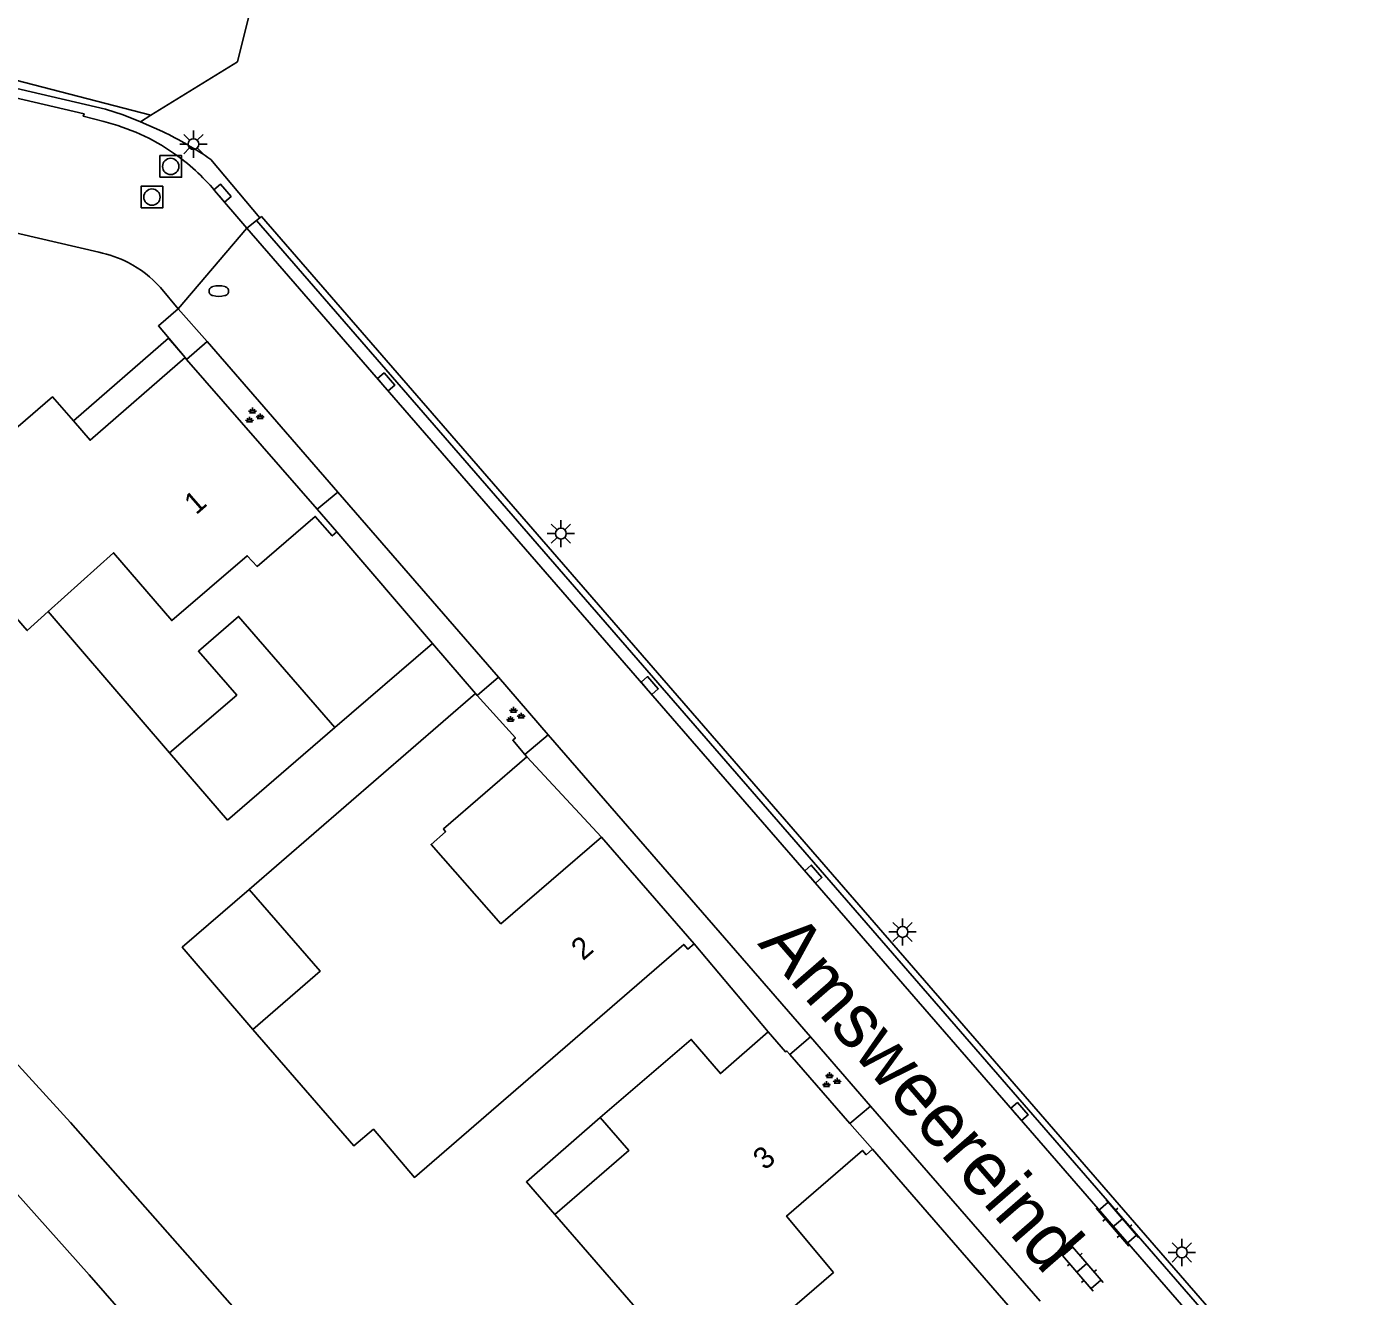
# Model space of a CAD drawing. Extents: x 128999 to 131010, y 395498 to 399007.
# Drawn here: x 129282.9 to 129344, y 397464.4 to 397522.8 of the extents above; entities that cross this region are included whole.
import ezdxf

# ---------------------------------------------------------------- set-up
doc = ezdxf.new("R2010")
doc.units = 0
for name, color, linetype in [('gg-afsc-faunaraster', 7, 'Continuous'), ('gg-afsc-muur', 7, 'Continuous'), ('gg-anno-huisnummerreeks BGT', 7, 'Continuous'), ('gg-anno-openbare ruimte label', 7, 'Continuous'), ('gg-bbg-bijgebouw', 7, 'Continuous'), ('gg-bbg-hoofdgebouw', 7, 'Continuous'), ('gg-bbg-luifel en loopbrug', 7, 'Continuous'), ('gg-bbg-onder overbouw', 7, 'Continuous'), ('gg-bbg-pand overbouw', 7, 'Continuous'), ('gg-knt-verharding', 7, 'Continuous'), ('gg-knt-verharding nz', 7, 'Continuous'), ('gg-kntw-bovenkant insteek waterloop', 7, 'Continuous'), ('gg-kntw-waterlijn', 7, 'Continuous'), ('gt-grn-groengrens', 7, 'Continuous'), ('gt-grn-weggrens', 7, 'Continuous'), ('gt-symb-brandkraan', 7, 'Continuous'), ('gt-symb-groenvak', 7, 'Continuous'), ('gt-symb-klinker verharding', 7, 'Continuous'), ('gt-symb-kolk', 7, 'Continuous'), ('gt-symb-lichtmast', 7, 'Continuous'), ('gt-symb-rioolschacht', 7, 'Continuous')]:
    doc.layers.add(name, color=color, linetype=linetype)

# ---------------------------------------------------------------- blocks, each defined once
blk = doc.blocks.new('gt0-LMAST')
at = {"layer": 'gt-symb-lichtmast'}
for p, q in [((-0.005, 0.246), (-0.005, 0.621)), ((-0.182, 0.173), (-0.447, 0.438)), ((0.172, 0.173), (0.437, 0.438)), ((-0.255, -0.004), (-0.63, -0.004)), ((-0.182, -0.181), (-0.447, -0.446)), ((-0.005, -0.254), (-0.005, -0.629)), ((0.437, -0.446), (0.172, -0.181)), ((0.245, -0.004), (0.62, -0.004))]:
    blk.add_line(p, q, dxfattribs=at)
blk.add_circle((-0.005, -0.004), 0.25, dxfattribs=at)
blk = doc.blocks.new('gt0-KOLK')
at = {"layer": 'gt-symb-kolk'}
blk.add_lwpolyline([(0, 0), (0.375, 0), (0.375, 0.4), (-0.375, 0.4), (-0.375, 0), (0, 0)], dxfattribs=at)
blk = doc.blocks.new('gt0-KL1')
at = {"layer": 'gt-symb-klinker verharding'}
for p, q in [((-1.15, 0.3), (1.15, 0.3)), ((-1, -0.3), (-1, 0.3)), ((-0.5, 0.3), (-0.5, 0.45)), ((0, -0.3), (0, 0.3)), ((0.5, 0.3), (0.5, 0.45)), ((1, -0.3), (1, 0.3)), ((-1.15, -0.3), (1.15, -0.3)), ((-0.5, -0.45), (-0.5, -0.3)), ((0.5, -0.45), (0.5, -0.3))]:
    blk.add_line(p, q, dxfattribs=at)
blk = doc.blocks.new('gt0-GRVAK')
at = {"layer": 'gt-symb-groenvak'}
for p, q in [((-0.11, 0.189), (-0.228, 0.24)), ((-0.182, 0.153), (0.088, 0.153)), ((-0.091, 0.211), (-0.156, 0.322)), ((-0.047, 0.214), (-0.047, 0.393)), ((-0.004, 0.211), (0.061, 0.322)), ((0.015, 0.189), (0.133, 0.24)), ((0.262, -0.052), (0.197, 0.059)), ((0.305, -0.049), (0.305, 0.13)), ((0.349, -0.052), (0.414, 0.059)), ((-0.245, -0.228), (-0.363, -0.177)), ((-0.318, -0.264), (-0.047, -0.264)), ((-0.226, -0.206), (-0.291, -0.095)), ((-0.183, -0.203), (-0.183, -0.024)), ((-0.139, -0.206), (-0.074, -0.095)), ((-0.12, -0.228), (-0.002, -0.177)), ((0.243, -0.074), (0.125, -0.023)), ((0.17, -0.11), (0.441, -0.11)), ((0.368, -0.074), (0.486, -0.023))]:
    blk.add_line(p, q, dxfattribs=at)
blk = doc.blocks.new('gt0-RS')
at = {"layer": 'gt-symb-rioolschacht'}
blk.add_lwpolyline([(-0.5, -0.5), (0.5, -0.5), (0.5, 0.5), (-0.5, 0.5)], close=True, dxfattribs=at)
blk.add_circle((0, 0), 0.375, dxfattribs=at)
blk = doc.blocks.new('gt0-BR')
at = {"layer": 'gt-symb-brandkraan'}
for centre, radius, start, end in [((-0.244, 0), 0.206, 107.56694, 252.43307), ((0.599, -2.664), 3, 106.89205, 107.56694), ((0, -0.691), 0.938, 73.10799, 106.89205), ((-0.599, -2.664), 3, 72.43309, 73.10799), ((0.244, 0), 0.206, 287.56695, 72.43309), ((0.599, 2.664), 3, 252.43307, 253.10797), ((0, 0.691), 0.938, 253.10797, 286.89206), ((-0.599, 2.664), 3, 286.89206, 287.56695)]:
    blk.add_arc(centre, radius, start, end, dxfattribs=at)

msp = doc.modelspace()

# ---------------------------------------------------------------- linework, layer by layer
at = {"layer": 'gg-afsc-faunaraster'}
for p, q in [((129289.126, 397518.003), (129288.116, 397518.456)), ((129293.598, 397514.027), (129291.348, 397516.722))]:
    msp.add_line(p, q, dxfattribs=at)
msp.add_lwpolyline([(129265.267, 397528.956), (129264.121, 397524.258), (129286.501, 397519.035), (129287.315, 397518.765), (129288.116, 397518.456)], dxfattribs=at)
msp.add_arc((129280.986, 397501.316), 18.566, 56.07553, 63.99691, dxfattribs=at)
at = {"layer": 'gg-afsc-muur'}
msp.add_line((129293.598, 397514.027), (129293.453, 397513.907), dxfattribs=at)
for points in [[(129339.555, 397452.636), (129343.606, 397456.151), (129293.453, 397513.907)], [(129338.819, 397451.59), (129344.015, 397456.113), (129293.672, 397514.088), (129293.598, 397514.027)]]:
    msp.add_lwpolyline(points, dxfattribs=at)
at = {"layer": 'gg-bbg-bijgebouw'}
for p, q in [((129297.055, 397490.584), (129292.119, 397486.323)), ((129292.119, 397486.323), (129289.448, 397489.428))]:
    msp.add_line(p, q, dxfattribs=at)
msp.add_lwpolyline([(129289.448, 397489.428), (129292.537, 397492.085), (129290.775, 397494.099), (129292.624, 397495.702), (129297.055, 397490.584)], dxfattribs=at)
at = {"layer": 'gg-bbg-hoofdgebouw'}
for p, q in [((129290.235, 397507.518), (129290.16, 397507.605)), ((129296.234, 397500.635), (129290.235, 397507.518)), ((129297.138, 397499.598), (129296.234, 397500.635)), ((129293.119, 397483.137), (129303.529, 397492.148)), ((129303.529, 397492.148), (129303.608, 397492.06)), ((129305.796, 397489.355), (129305.887, 397489.249)), ((129309.32, 397485.548), (129313.587, 397480.648)), ((129317.997, 397475.546), (129320.755, 397472.381)), ((129320.755, 397472.381), (129321.793, 397471.19))]:
    msp.add_line(p, q, dxfattribs=at)
for points in [[(129278.065, 397500.628), (129284.065, 397505.793), (129285.023, 397504.691)], [(129278.301, 397500.353), (129282.898, 397495.047), (129283.864, 397495.919)], [(129283.864, 397495.919), (129286.871, 397498.632), (129289.553, 397495.506), (129293.022, 397498.488), (129293.487, 397497.997), (129296.154, 397500.302), (129296.932, 397499.401), (129297.138, 397499.598)], [(129303.608, 397492.06), (129305.361, 397490.109), (129305.239, 397490.003), (129305.796, 397489.355)], [(129305.887, 397489.249), (129302.052, 397485.925), (129302.152, 397485.794), (129301.486, 397485.216), (129304.692, 397481.563), (129309.32, 397485.548)], [(129293.284, 397476.699), (129296.376, 397479.377), (129293.119, 397483.137)], [(129313.587, 397480.648), (129313.303, 397480.394), (129313.112, 397480.615), (129300.717, 397469.899), (129298.828, 397472.11), (129297.933, 397471.346), (129293.284, 397476.699)], [(129309.265, 397472.647), (129313.457, 397476.244), (129314.794, 397474.67), (129316.997, 397476.594)], [(129316.997, 397476.594), (129317.793, 397475.668), (129317.854, 397475.71), (129317.997, 397475.546)], [(129321.793, 397471.19), (129321.506, 397470.936), (129321.332, 397471.136), (129317.841, 397468.115), (129319.996, 397465.524), (129313.981, 397460.343), (129307.177, 397468.195)]]:
    msp.add_lwpolyline(points, dxfattribs=at)
at = {"layer": 'gg-bbg-luifel en loopbrug'}
for p, q in [((129301.552, 397494.453), (129297.138, 397499.598)), ((129289.448, 397489.428), (129283.864, 397495.919)), ((129297.055, 397490.584), (129301.552, 397494.453))]:
    msp.add_line(p, q, dxfattribs=at)
msp.add_lwpolyline([(129293.119, 397483.137), (129290.031, 397480.481), (129293.284, 397476.699)], dxfattribs=at)
at = {"layer": 'gg-bbg-onder overbouw'}
for points in [[(129290.16, 397507.605), (129285.793, 397503.806), (129285.023, 397504.691)], [(129307.177, 397468.195), (129310.575, 397471.131), (129309.265, 397472.647)]]:
    msp.add_lwpolyline(points, dxfattribs=at)
at = {"layer": 'gg-bbg-pand overbouw'}
for points in [[(129290.16, 397507.605), (129289.395, 397508.495), (129285.023, 397504.691)], [(129309.265, 397472.647), (129305.871, 397469.689), (129307.177, 397468.195)]]:
    msp.add_lwpolyline(points, dxfattribs=at)
at = {"layer": 'gg-knt-verharding'}
for p, q in [((129291.523, 397515.286), (129293.011, 397513.551)), ((129293.011, 397513.551), (129293.453, 397513.907)), ((129281.318, 397513.58), (129286.19, 397512.447)), ((129289.031, 397510.824), (129289.843, 397509.855)), ((129291.176, 397508.339), (129290.235, 397507.518)), ((129297.19, 397501.416), (129291.176, 397508.339)), ((129296.234, 397500.635), (129297.19, 397501.416)), ((129303.529, 397492.148), (129301.552, 397494.453)), ((129304.583, 397492.904), (129303.608, 397492.06)), ((129306.87, 397490.259), (129304.583, 397492.904)), ((129305.796, 397489.355), (129306.87, 397490.259)), ((129309.32, 397485.548), (129305.887, 397489.249)), ((129316.997, 397476.594), (129313.587, 397480.648)), ((129318.935, 397476.366), (129317.997, 397475.546)), ((129321.7, 397473.177), (129318.935, 397476.366)), ((129320.755, 397472.381), (129321.7, 397473.177)), ((129328.042, 397464.007), (129321.793, 397471.19))]:
    msp.add_line(p, q, dxfattribs=at)
for points in [[(129253.95, 397526.195), (129285.519, 397518.824), (129285.476, 397518.704), (129286.423, 397518.457)], [(129293.011, 397513.551), (129342.782, 397456.241), (129339.158, 397453.089)], [(129289.843, 397509.855), (129288.934, 397509.059), (129290.16, 397507.605)]]:
    msp.add_lwpolyline(points, dxfattribs=at)
for centre, radius, start, end in [((129284.137, 397509.099), 9.633, 55.22858, 76.27435), ((129284.153, 397509.108), 9.617, 39.9752, 55.27877), ((129285.18, 397507.397), 5.15, 62.66869, 78.69473), ((129285.166, 397507.357), 5.192, 41.8934, 62.73129)]:
    msp.add_arc(centre, radius, start, end, dxfattribs=at)
at = {"layer": 'gg-knt-verharding nz'}
for p, q in [((129289.843, 397509.855), (129291.176, 397508.339)), ((129304.583, 397492.904), (129297.19, 397501.416)), ((129318.935, 397476.366), (129306.87, 397490.259)), ((129329.505, 397464.205), (129321.7, 397473.177))]:
    msp.add_line(p, q, dxfattribs=at)
at = {"layer": 'gg-kntw-bovenkant insteek waterloop'}
msp.add_lwpolyline([(129318.117, 397433.675), (129315.674, 397436.634), (129300.352, 397454.892), (129284.891, 397472.426), (129273.705, 397484.651), (129269.009, 397490.892)], dxfattribs=at)
at = {"layer": 'gg-kntw-waterlijn'}
msp.add_lwpolyline([(129317, 397430.593), (129316.504, 397430.431), (129311.71, 397434.831), (129300.146, 397448.923), (129285.744, 397465.423), (129277.504, 397474.652), (129266.687, 397485.837), (129263.561, 397488.271), (129261.443, 397491.391)], dxfattribs=at)
at = {"layer": 'gt-grn-groengrens'}
msp.add_line((129288.594, 397518.763), (129288.116, 397518.456), dxfattribs=at)
for points in [[(129288.594, 397518.763), (129292.578, 397521.211), (129293.188, 397523.677), (129288.934, 397529.654)], [(129265.267, 397528.956), (129264.967, 397524.881), (129288.594, 397518.763)]]:
    msp.add_lwpolyline(points, dxfattribs=at)
at = {"layer": 'gt-grn-weggrens'}
msp.add_line((129289.843, 397509.855), (129293.011, 397513.551), dxfattribs=at)

# ---------------------------------------------------------------- block references
at = {"layer": 'gt-symb-brandkraan'}
msp.add_blockref('gt0-BR', (129291.716, 397510.662), dxfattribs=at)
at = {"layer": 'gt-symb-groenvak'}
for p in [(129293.309, 397504.911), (129305.321, 397491.143), (129319.863, 397474.345)]:
    msp.add_blockref('gt0-GRVAK', p, dxfattribs=at)
at = {"layer": 'gt-symb-klinker verharding'}
for p, rotation in [((129333.063, 397467.803), -49.29925519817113), ((129331.428, 397465.738), -49.29925519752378)]:
    msp.add_blockref('gt0-KL1', p, dxfattribs=dict(at, rotation=rotation))
at = {"layer": 'gt-symb-kolk'}
for p, rotation in [((129291.734, 397515.04), -49.151881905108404), ((129299.261, 397506.354), -48.9689381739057), ((129311.389, 397492.389), -49.03195155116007), ((129318.922, 397483.715), -49.031951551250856), ((129328.406, 397472.795), -49.031951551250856)]:
    msp.add_blockref('gt0-KOLK', p, dxfattribs=dict(at, rotation=rotation))
at = {"layer": 'gt-symb-lichtmast'}
for p in [(129290.554, 397517.427), (129307.46, 397499.513), (129323.18, 397481.191), (129336.033, 397466.45)]:
    msp.add_blockref('gt0-LMAST', p, dxfattribs=at)
at = {"layer": 'gt-symb-rioolschacht'}
for p in [(129289.502, 397516.397), (129288.637, 397514.986)]:
    msp.add_blockref('gt0-RS', p, dxfattribs=at)

# ---------------------------------------------------------------- texts
at = {"layer": 'gg-anno-huisnummerreeks BGT'}
for s, rotation, p in [('1', 41.1, (129290.668, 397500.341)), ('2', 41, (129308.472, 397479.839)), ('3', 41.1, (129316.843, 397470.19))]:
    msp.add_text(s, height=1, rotation=rotation, dxfattribs=at).set_placement(p)
at = {"layer": 'gg-anno-openbare ruimte label'}
msp.add_text('Amsweereind', height=2.5, rotation=311, dxfattribs=at).set_placement((129316.475, 397480.632))

doc.saveas('drawing.dxf')
